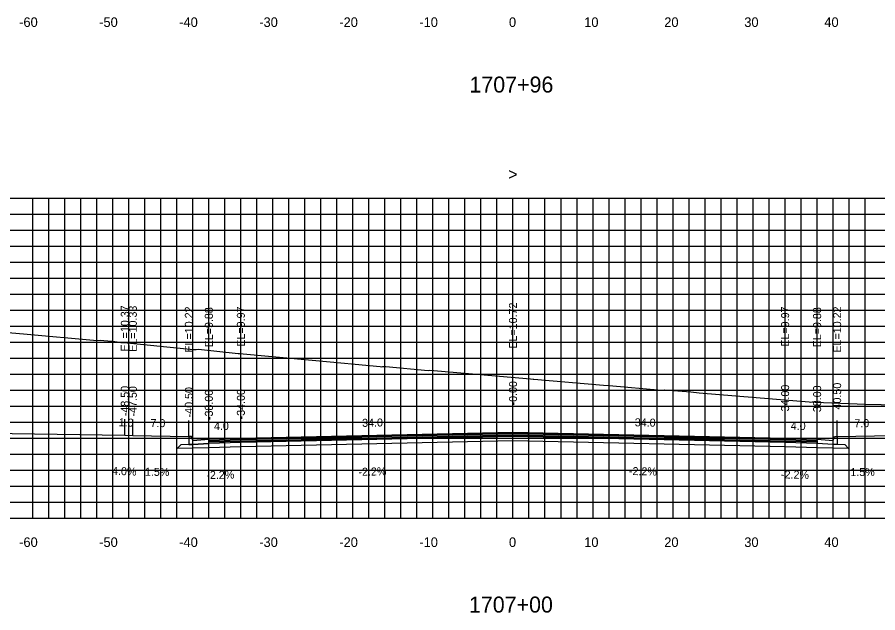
# Model space of a CAD drawing. Extents: x 1797789 to 1803805, y 249066 to 250293.
# Drawn here: x 1803249.1 to 1803356.6, y 250087.6 to 250162 of the extents above; entities that cross this region are included whole.
import ezdxf

# ---------------------------------------------------------------- set-up
doc = ezdxf.new("R2010")
doc.units = 0
for name, color, linetype in [('1', 7, 'Continuous'), ('10', 7, 'Continuous'), ('3', 7, 'Continuous'), ('4', 7, 'Continuous'), ('60', 7, 'Continuous'), ('BASE', 7, 'Continuous'), ('CL-CNST', 7, 'Continuous'), ('Level 62', 7, 'Continuous'), ('LOWER BINDER', 7, 'Continuous'), ('M-ROADS', 7, 'Continuous'), ('UPPER BINDER', 7, 'Continuous'), ('WEARING', 7, 'Continuous')]:
    doc.layers.add(name, color=color, linetype=linetype)

msp = doc.modelspace()

# ---------------------------------------------------------------- linework, layer by layer
for p, q in [((1803311, 250110.15), (1803311, 250112.15)), ((1803262.5, 250109.8), (1803262.5, 250111.8)), ((1803263.5, 250109.76), (1803263.5, 250111.76)), ((1803270.5, 250109.65), (1803270.5, 250111.65)), ((1803270.5, 250109.65), (1803270.5, 250111.65)), ((1803273, 250109.31), (1803273, 250111.31)), ((1803277, 250109.4), (1803277, 250111.4)), ((1803345, 250109.4), (1803345, 250111.4)), ((1803349, 250109.31), (1803349, 250111.31)), ((1803351.5, 250109.65), (1803351.5, 250111.65)), ((1803351.5, 250109.65), (1803351.5, 250111.65))]:
    msp.add_line(p, q)
for points in [[(1803273, 250109.31), (1803271, 250109.15), (1803270.83, 250109.65), (1803270.5, 250109.65), (1803270.5, 250108.62), (1803271, 250108.62), (1803273, 250108.78)], [(1803349, 250109.31), (1803351, 250109.15), (1803351.17, 250109.65), (1803351.5, 250109.65), (1803351.5, 250108.62), (1803351, 250108.62), (1803349, 250108.78)]]:
    msp.add_lwpolyline(points, close=True)
at = {"layer": '60'}
for p, q in [((1803161, 250099.43), (1803461, 250099.43)), ((1803251, 250099.37), (1803251, 250099.43)), ((1803261, 250099.37), (1803261, 250099.43)), ((1803271, 250099.37), (1803271, 250099.43)), ((1803281, 250099.37), (1803281, 250099.43)), ((1803291, 250099.37), (1803291, 250099.43)), ((1803301, 250099.37), (1803301, 250099.43)), ((1803311, 250099.37), (1803311, 250099.43)), ((1803321, 250099.37), (1803321, 250099.43)), ((1803331, 250099.37), (1803331, 250099.43)), ((1803341, 250099.37), (1803341, 250099.43)), ((1803351, 250099.37), (1803351, 250099.43))]:
    msp.add_line(p, q, dxfattribs=at)
at = {"layer": 'BASE'}
msp.add_lwpolyline([(1803349, 250108.28), (1803352.9, 250108.2), (1803352.5, 250108.6), (1803351.5, 250108.62), (1803351, 250108.62), (1803349, 250108.78), (1803345, 250108.87), (1803311, 250109.62), (1803277, 250108.87), (1803273, 250108.78), (1803271, 250108.62), (1803270.5, 250108.62), (1803269.5, 250108.6), (1803269.1, 250108.2), (1803273, 250108.28), (1803277, 250108.37), (1803311, 250109.12), (1803345, 250108.37)], close=True, dxfattribs=at)
at = {"layer": 'CL-CNST'}
msp.add_lwpolyline([(1803161, 250111.29), (1803262.5, 250109.8), (1803263.5, 250109.76), (1803270.5, 250109.65), (1803270.5, 250109.65), (1803270.83, 250109.65), (1803271, 250109.15), (1803273, 250109.31), (1803277, 250109.4), (1803311, 250110.15), (1803345, 250109.4), (1803349, 250109.31), (1803351, 250109.15), (1803351.17, 250109.65), (1803351.5, 250109.65), (1803351.5, 250109.65), (1803358.5, 250109.76), (1803359.5, 250109.8), (1803461, 250109.89)], dxfattribs=at)
at = {"layer": 'Level 62'}
for p, q in [((1803161, 250139.43), (1803461, 250139.43)), ((1803251, 250099.43), (1803251, 250139.43)), ((1803253, 250099.43), (1803253, 250139.43)), ((1803255, 250099.43), (1803255, 250139.43)), ((1803257, 250099.43), (1803257, 250139.43)), ((1803259, 250099.43), (1803259, 250139.43)), ((1803261, 250099.43), (1803261, 250139.43)), ((1803263, 250099.43), (1803263, 250139.43)), ((1803265, 250099.43), (1803265, 250139.43)), ((1803267, 250099.43), (1803267, 250139.43)), ((1803269, 250099.43), (1803269, 250139.43)), ((1803271, 250099.43), (1803271, 250139.43)), ((1803273, 250099.43), (1803273, 250139.43)), ((1803275, 250099.43), (1803275, 250139.43)), ((1803277, 250099.43), (1803277, 250139.43)), ((1803279, 250099.43), (1803279, 250139.43)), ((1803281, 250099.43), (1803281, 250139.43)), ((1803283, 250099.43), (1803283, 250139.43)), ((1803285, 250099.43), (1803285, 250139.43)), ((1803287, 250099.43), (1803287, 250139.43)), ((1803289, 250099.43), (1803289, 250139.43)), ((1803291, 250099.43), (1803291, 250139.43)), ((1803293, 250099.43), (1803293, 250139.43)), ((1803295, 250099.43), (1803295, 250139.43)), ((1803297, 250099.43), (1803297, 250139.43)), ((1803299, 250099.43), (1803299, 250139.43)), ((1803301, 250099.43), (1803301, 250139.43)), ((1803303, 250099.43), (1803303, 250139.43)), ((1803305, 250099.43), (1803305, 250139.43)), ((1803307, 250099.43), (1803307, 250139.43)), ((1803309, 250099.43), (1803309, 250139.43)), ((1803311, 250099.43), (1803311, 250139.43)), ((1803313, 250099.43), (1803313, 250139.43)), ((1803315, 250099.43), (1803315, 250139.43)), ((1803317, 250099.43), (1803317, 250139.43)), ((1803319, 250099.43), (1803319, 250139.43)), ((1803321, 250099.43), (1803321, 250139.43)), ((1803323, 250099.43), (1803323, 250139.43)), ((1803325, 250099.43), (1803325, 250139.43)), ((1803327, 250099.43), (1803327, 250139.43)), ((1803329, 250099.43), (1803329, 250139.43)), ((1803331, 250099.43), (1803331, 250139.43)), ((1803333, 250099.43), (1803333, 250139.43)), ((1803335, 250099.43), (1803335, 250139.43)), ((1803337, 250099.43), (1803337, 250139.43)), ((1803339, 250099.43), (1803339, 250139.43)), ((1803341, 250099.43), (1803341, 250139.43)), ((1803343, 250099.43), (1803343, 250139.43)), ((1803345, 250099.43), (1803345, 250139.43)), ((1803347, 250099.43), (1803347, 250139.43)), ((1803349, 250099.43), (1803349, 250139.43)), ((1803351, 250099.43), (1803351, 250139.43)), ((1803353, 250099.43), (1803353, 250139.43)), ((1803355, 250099.43), (1803355, 250139.43)), ((1803161, 250137.43), (1803461, 250137.43)), ((1803161, 250135.43), (1803461, 250135.43)), ((1803161, 250133.43), (1803461, 250133.43)), ((1803161, 250131.43), (1803461, 250131.43)), ((1803161, 250129.43), (1803461, 250129.43)), ((1803161, 250127.43), (1803461, 250127.43)), ((1803161, 250125.43), (1803461, 250125.43)), ((1803161, 250123.43), (1803461, 250123.43)), ((1803161, 250121.43), (1803461, 250121.43)), ((1803161, 250119.43), (1803461, 250119.43)), ((1803161, 250117.43), (1803461, 250117.43)), ((1803161, 250115.43), (1803461, 250115.43)), ((1803161, 250113.43), (1803461, 250113.43)), ((1803161, 250111.43), (1803461, 250111.43)), ((1803161, 250109.43), (1803461, 250109.43)), ((1803161, 250107.43), (1803461, 250107.43)), ((1803161, 250105.43), (1803461, 250105.43)), ((1803161, 250103.43), (1803461, 250103.43)), ((1803161, 250101.43), (1803461, 250101.43)), ((1803161, 250099.43), (1803461, 250099.43))]:
    msp.add_line(p, q, dxfattribs=at)
at = {"layer": 'LOWER BINDER'}
msp.add_lwpolyline([(1803273, 250108.78), (1803273, 250108.97), (1803277, 250109.06), (1803311, 250109.81), (1803345, 250109.06), (1803349, 250108.97), (1803349, 250108.78), (1803345, 250108.87), (1803311, 250109.62), (1803277, 250108.87)], close=True, dxfattribs=at)
at = {"layer": 'M-ROADS'}
msp.add_lwpolyline([(1803241.54, 250123.2), (1803249.84, 250122.48), (1803259.05, 250121.65), (1803259.41, 250121.68), (1803260.83, 250121.56), (1803260.98, 250121.54), (1803261.53, 250121.47), (1803271.1, 250120.53), (1803271.42, 250120.53), (1803271.7, 250120.54), (1803276.66, 250120.02), (1803276.81, 250120.03), (1803285.92, 250119.19), (1803286.36, 250119.14), (1803294.4, 250118.39), (1803294.62, 250118.35), (1803294.75, 250118.37), (1803294.98, 250118.39), (1803295.11, 250118.37), (1803300.41, 250117.91), (1803300.61, 250117.92), (1803313.2, 250116.84), (1803313.54, 250116.79), (1803313.59, 250116.79), (1803322.3, 250116.04), (1803323.03, 250116.01), (1803329.55, 250115.45), (1803329.93, 250115.47), (1803329.96, 250115.48), (1803333.21, 250115.21), (1803334.26, 250115.11), (1803348.02, 250113.96), (1803348.17, 250113.94), (1803348.38, 250113.96), (1803348.53, 250113.98), (1803348.74, 250113.95), (1803355.06, 250113.69), (1803366.89, 250113.44)], dxfattribs=at)
at = {"layer": 'UPPER BINDER'}
msp.add_lwpolyline([(1803311, 250109.81), (1803277, 250109.06), (1803273, 250108.97), (1803273, 250109.16), (1803277, 250109.25), (1803311, 250110), (1803345, 250109.25), (1803349, 250109.16), (1803349, 250108.78), (1803349, 250108.97), (1803345, 250109.06)], close=True, dxfattribs=at)
at = {"layer": 'WEARING'}
msp.add_lwpolyline([(1803349, 250109.16), (1803349, 250109.31), (1803345, 250109.4), (1803311, 250110.15), (1803277, 250109.4), (1803273, 250109.31), (1803273, 250109.16), (1803277, 250109.25), (1803311, 250110), (1803345, 250109.25)], close=True, dxfattribs=at)

# ---------------------------------------------------------------- texts
at = {"layer": '1'}
for s, p in [('1707+96', (1803305.56, 250152.63)), ('1707+00', (1803305.5, 250087.63))]:
    msp.add_text(s, height=2, dxfattribs=at).set_placement(p)
at = {"layer": '10'}
for s, p in [('-60', (1803249.3, 250160.83)), ('-50', (1803259.3, 250160.83)), ('-40', (1803269.3, 250160.83)), ('-30', (1803279.3, 250160.83)), ('-20', (1803289.3, 250160.83)), ('-10', (1803299.3, 250160.83)), ('0', (1803310.5, 250160.83)), ('10', (1803319.9, 250160.83)), ('20', (1803329.9, 250160.83)), ('30', (1803339.9, 250160.83)), ('40', (1803349.9, 250160.83)), ('-60', (1803249.3, 250095.83)), ('-50', (1803259.3, 250095.83)), ('-40', (1803269.3, 250095.83)), ('-30', (1803279.3, 250095.83)), ('-20', (1803289.3, 250095.83)), ('-10', (1803299.3, 250095.83)), ('0', (1803310.5, 250095.83)), ('10', (1803319.9, 250095.83)), ('20', (1803329.9, 250095.83)), ('30', (1803339.9, 250095.83)), ('40', (1803349.9, 250095.83))]:
    msp.add_text(s, height=1.2, dxfattribs=at).set_placement(p)
at = {"layer": '3'}
for s, p in [('EL=10.37', (1803263, 250120.27)), ('EL=10.33', (1803264, 250120.23)), ('EL=10.72', (1803311.5, 250120.62)), ('EL=10.22', (1803271, 250120.13)), ('EL=10.22', (1803271, 250120.13)), ('EL=9.88', (1803273.5, 250120.78)), ('EL=9.97', (1803277.5, 250120.87)), ('EL=9.97', (1803345.5, 250120.87)), ('EL=9.88', (1803349.5, 250120.78)), ('EL=10.22', (1803352, 250120.13)), ('EL=10.22', (1803352, 250120.13)), ('-0.00', (1803311.5, 250113.52)), ('40.50', (1803352, 250113.02)), ('40.50', (1803352, 250113.02)), ('-48.50', (1803263, 250112.18)), ('-47.50', (1803264, 250112.14)), ('-40.50', (1803271, 250112.03)), ('-40.50', (1803271, 250112.03)), ('-38.00', (1803273.5, 250111.69)), ('-34.00', (1803277.5, 250111.78)), ('34.00', (1803345.5, 250112.77)), ('38.00', (1803349.5, 250112.68))]:
    msp.add_text(s, height=1, rotation=90, dxfattribs=at).set_placement(p)
at = {"layer": '4'}
for s, rotation, p in [('1.0', 357.7094, (1803261.72, 250110.93)), ('34.0', 1.2603, (1803292.16, 250110.84)), ('34.0', 358.7397, (1803326.21, 250110.92)), ('7.0', 359.1406, (1803265.7, 250110.83)), ('4.0', 1.2603, (1803273.65, 250110.43)), ('4.0', 358.7397, (1803345.7, 250110.49)), ('7.0', 0.8594, (1803353.66, 250110.79)), ('4.0%', 357.7094, (1803260.89, 250104.86)), ('1.5%', 359.1406, (1803265.01, 250104.74)), ('-2.2%', 1.2603, (1803291.7, 250104.72)), ('-2.2%', 358.7397, (1803325.48, 250104.83)), ('-2.2%', 358.7397, (1803344.48, 250104.41)), ('1.5%', 0.8594, (1803353.16, 250104.68)), ('-2.2%', 1.2603, (1803272.7, 250104.31))]:
    msp.add_text(s, height=1, rotation=rotation, dxfattribs=at).set_placement(p)
at = {"layer": '60'}
msp.add_text('>', height=1.5, dxfattribs=at).set_placement((1803310.39, 250141.68))

doc.saveas('drawing.dxf')
